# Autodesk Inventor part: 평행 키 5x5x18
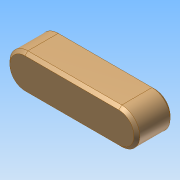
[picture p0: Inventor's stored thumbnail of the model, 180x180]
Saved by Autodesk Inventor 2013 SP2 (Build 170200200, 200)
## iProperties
Created: 2025-05
Part Number: 평행 키 5x5x18
Material: Generic
Document SubType Name: Modeling
Designer: a
Density: 1 g/cm^3
Author: a
변환 표준: STEP AP214IS
전처리기: Build: 200, Release: 2013 SP2 Update 6 - Date: Thu 07/17/2014
전송 단위: 밀리미터
불확실성: 0.01
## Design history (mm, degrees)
node "평행 키 5x5x181"
body "Solid1"
node "기준1"
